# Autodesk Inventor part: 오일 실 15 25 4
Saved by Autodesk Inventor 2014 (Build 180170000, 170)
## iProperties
Created: 2025-10
Part Number: 오일 실 15 25 4
Material: 일반
Document SubType Name: Modeling
Designer: dg
Density: 1 g/cm^3
Appearance: 기본값
Author: dg
Author: jhkim
Description: 오일 실 - 비스프링, 조립 GA
Creation Date: 2025-10-01
Sending System: Autodesk Inventor 2026
Preprocessor: ST-DEVELOPER v20.1
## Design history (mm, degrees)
node "오일 실 15 25 41"
body "Solid1"
node "기준1"
